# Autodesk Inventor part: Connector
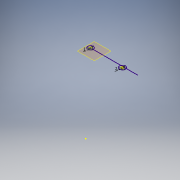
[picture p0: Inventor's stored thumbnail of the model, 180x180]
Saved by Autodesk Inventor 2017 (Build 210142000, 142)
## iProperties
Created: 2017-05
Part Number: Connector
Material: Generic
Document SubType Name: Modeling
Designer: 1717440
Density: 1 g/cm^3
Appearance: Default
Author: 1717440
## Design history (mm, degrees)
workplane "Work Plane1"
sketch "Sketch2"
  geometry: L1 (-10.669, -12.403)-(-12.056, -44.251); L2 (-6.668, -12.374)-(-8.055, -44.225); C1 r 1.587 at (-8.693, -8.925) reference; C2 r 1.587 at (-10.034, -47.702) reference; A1 r 2 centre (-8.693, -8.925) between (-6.698, -9.063) and (-10.693, -8.925); A2 r 4 centre (-8.693, -8.925) between (-4.703, -9.201) and (-12.693, -8.925); A3 r 2 centre (-10.034, -47.702) between (-12.029, -47.563) and (-8.034, -47.702); A4 r 4 centre (-10.034, -47.702) between (-14.024, -47.425) and (-6.034, -47.702); A5 r 4 centre (-8.693, -8.925) between (-12.693, -8.925) and (-10.669, -12.403); A6 r 4 centre (-10.034, -47.702) between (-6.034, -47.702) and (-12.056, -44.251); 3 further points
  constraints: 14 point on circle, 8 coincident, 6 centre point, 4 end point, 2 horizontal alignment, 4 other
  dimensions: "d2" = 4 diameter of A1; "d3" = 8 diameter of A2; "d4" = 4 diameter of A3; "d5" = 8 diameter of A4
  node "Reference3"
  node "Reference4"
workplane "Work Plane2"
workplane "Work Plane3"
extrude "Extrusion2" new body sketch "Sketch2" stored distance "d10" = 10; taper "d11" = 0 deg
body "Solid2"
